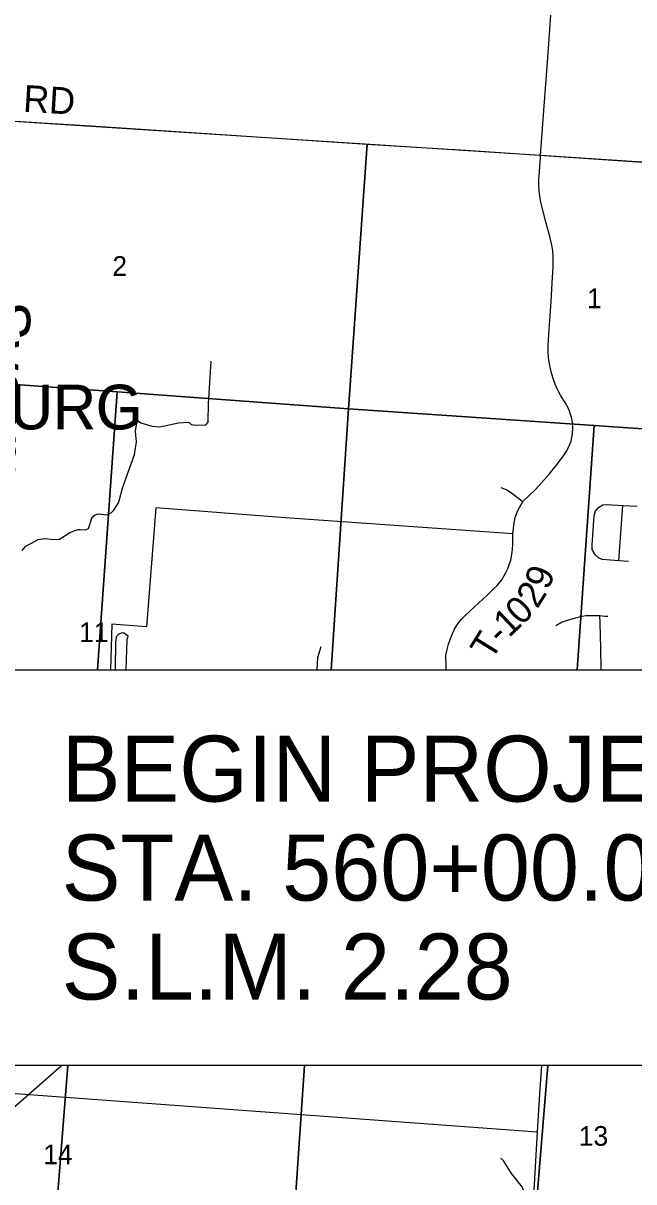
# Model space of a CAD drawing. Extents: x 0 to 34, y 0 to 26.1.
# Drawn here: x 28.22 to 29.516, y 18.306 to 20.765 of the extents above; entities that cross this region are included whole.
import ezdxf

# ---------------------------------------------------------------- set-up
doc = ezdxf.new("R2010")
doc.units = 0
for name, color, linetype in [('GM_X_Corporation_Text', 7, 'Continuous'), ('GM_X_Minor_Lake', 7, 'Continuous'), ('GM_X_Minor_River', 7, 'Continuous'), ('GM_X_Minor_River_Text', 7, 'Continuous'), ('GM_X_Section', 7, 'Continuous'), ('GM_X_Section_Text', 7, 'Continuous'), ('GM_X_Township_Road', 7, 'Continuous'), ('GM_X_Township_Road_Text', 7, 'Continuous'), ('SH_Data', 7, 'Continuous'), ('SH_Text', 7, 'Continuous')]:
    doc.layers.add(name, color=color, linetype=linetype)

msp = doc.modelspace()

# ---------------------------------------------------------------- linework, layer by layer
at = {"layer": 'GM_X_Minor_Lake'}
msp.add_line((28.4383, 19.3933), (28.4406, 19.4567), dxfattribs=at)
msp.add_lwpolyline([(28.4406, 19.4567), (28.4429, 19.4643), (28.4327, 19.4712), (28.4278, 19.4708), (28.4232, 19.4689), (28.4171, 19.4629), (28.416, 19.4511), (28.4159, 19.4306), (28.4152, 19.4173), (28.4154, 19.3933)], dxfattribs=at)
at = {"layer": 'GM_X_Minor_River'}
for points in [[(28.4071, 19.7271), (28.4124, 19.732), (28.4219, 19.7472), (28.4245, 19.7544), (28.431, 19.7786), (28.4565, 19.85), (28.4604, 19.8765), (28.4593, 19.8909), (28.4585, 19.9001), (28.4608, 19.9164), (28.4639, 19.9213), (28.4696, 19.9171), (28.4938, 19.9102), (28.5097, 19.909), (28.5498, 19.9173), (28.5714, 19.9184), (28.5763, 19.9138), (28.5866, 19.9119), (28.6078, 19.913), (28.6123, 19.9183), (28.6132, 19.9597), (28.6136, 19.9684), (28.619, 20.0481)], [(28.2176, 19.6459), (28.2259, 19.6554), (28.2453, 19.6663), (28.2517, 19.6694), (28.2661, 19.6716), (28.2846, 19.6693), (28.2971, 19.67), (28.3188, 19.6844), (28.3362, 19.6908), (28.3411, 19.6908), (28.3525, 19.6904), (28.3582, 19.6926), (28.3662, 19.7173), (28.373, 19.7222), (28.3794, 19.7241), (28.3984, 19.7222), (28.4071, 19.7271)], [(28.8438, 19.3933), (28.8453, 19.419), (28.8526, 19.4425)], [(29.2357, 17.9139), (29.2486, 17.9215), (29.2512, 17.9276), (29.2543, 17.9431), (29.2525, 18.0043), (29.2511, 18.0213), (29.248, 18.032), (29.2379, 18.0457), (29.2269, 18.0567), (29.2258, 18.0837), (29.2377, 18.1406), (29.248, 18.1747), (29.2575, 18.1948), (29.2704, 18.2142), (29.2852, 18.2282), (29.2886, 18.2331), (29.2886, 18.2396), (29.2883, 18.246), (29.2849, 18.2817), (29.2793, 18.2958), (29.2562, 18.3243), (29.24, 18.3502), (29.2336, 18.3566)]]:
    msp.add_lwpolyline(points, dxfattribs=at)
at = {"layer": 'GM_X_Section'}
for points in [[(27.9376, 20.5735), (28.3638, 20.5476), (28.9502, 20.5089), (28.9104, 19.9472), (28.4191, 19.9828), (27.9001, 20.0205)], [(28.9502, 20.5089), (29.1456, 20.4964), (29.1491, 20.4962), (29.6694, 20.4609), (29.9551, 20.4402), (29.9161, 19.8781), (29.4315, 19.9112), (28.9104, 19.9472)]]:
    msp.add_lwpolyline(points, close=True, dxfattribs=at)
for points in [[(28.1615, 19.0015), (27.8314, 19.025), (27.9001, 20.0205), (28.4191, 19.9828), (28.3774, 19.3933)], [(28.3774, 19.3933), (28.4191, 19.9828), (28.9104, 19.9472), (28.8738, 19.3933)], [(28.8738, 19.3933), (28.9104, 19.9472), (29.4315, 19.9112), (29.3959, 19.3933)], [(29.3959, 19.3933), (29.4315, 19.9112), (29.9161, 19.8781), (29.8466, 18.8822), (29.8402, 18.8827)], [(28.3147, 18.5533), (28.2704, 17.9878), (27.7604, 18.0248), (27.8314, 19.025), (28.1615, 19.0015)], [(28.8173, 18.5533), (28.776, 17.9511), (28.2704, 17.9878), (28.3147, 18.5533)], [(29.3334, 18.5533), (29.2811, 17.9144), (28.776, 17.9511), (28.8173, 18.5533)], [(29.825, 18.5533), (29.7809, 17.8804), (29.2811, 17.9144), (29.3334, 18.5533)]]:
    msp.add_lwpolyline(points, dxfattribs=at)
at = {"layer": 'GM_X_Township_Road'}
for p, q in [((29.4838, 19.6246), (29.4925, 19.742)), ((28.012, 18.5079), (29.3107, 18.4123)), ((29.3107, 18.4123), (29.297, 18.1618))]:
    msp.add_line(p, q, dxfattribs=at)
for points in [[(29.3177, 20.4844), (29.3247, 20.5799), (29.3328, 20.6825), (29.3477, 20.8931), (29.3482, 20.9)], [(29.9005, 20.446), (29.3177, 20.4844), (28.111, 20.5622)], [(29.1175, 19.3933), (29.1174, 19.4006), (29.1172, 19.4239), (29.1195, 19.4364), (29.1228, 19.4472), (29.1259, 19.4571), (29.1302, 19.4681), (29.1353, 19.4793), (29.1394, 19.4862), (29.1445, 19.4934), (29.1501, 19.5003), (29.1586, 19.5089), (29.2045, 19.5516), (29.2163, 19.5626), (29.2257, 19.5723), (29.2357, 19.5843), (29.2433, 19.5983), (29.2482, 19.6078), (29.2515, 19.6162), (29.2546, 19.6254), (29.2561, 19.6338), (29.2584, 19.6481), (29.2591, 19.6598), (29.2589, 19.6815), (29.2617, 19.7052), (29.264, 19.7166), (29.2695, 19.7312), (29.2807, 19.75), (29.3064, 19.7753), (29.3201, 19.7896), (29.3362, 19.8084), (29.3514, 19.8266), (29.3669, 19.8471), (29.3723, 19.8555), (29.3782, 19.8663), (29.3828, 19.8784), (29.3859, 19.8939), (29.3864, 19.9056), (29.3857, 19.9185), (29.3839, 19.929), (29.3783, 19.9462), (29.3703, 19.9602), (29.3611, 19.9743), (29.3538, 19.9879), (29.3489, 19.9993), (29.3445, 20.0113), (29.3403, 20.0251), (29.3367, 20.0422), (29.335, 20.0558), (29.334, 20.0672), (29.3341, 20.0807), (29.3357, 20.1055), (29.3402, 20.1744), (29.3424, 20.2143), (29.3448, 20.2478), (29.3451, 20.2563), (29.3448, 20.2682), (29.3437, 20.2827), (29.3419, 20.2943), (29.3378, 20.3124), (29.3301, 20.3411), (29.3236, 20.3657), (29.3193, 20.3825), (29.317, 20.393), (29.3149, 20.4095), (29.3142, 20.4234), (29.3144, 20.4343), (29.3148, 20.4415), (29.3176, 20.4806), (29.3177, 20.4844)], [(29.2336, 19.78), (29.2394, 19.7779), (29.2462, 19.7748), (29.2541, 19.77), (29.2807, 19.75)], [(29.2589, 19.6815), (28.7767, 19.7158), (28.5012, 19.7365), (28.4815, 19.4845), (28.4078, 19.4898), (28.405, 19.3933)], [(29.5043, 19.623), (29.4838, 19.6246), (29.4485, 19.6273), (29.4408, 19.6305), (29.4346, 19.6366), (29.4278, 19.6484), (29.4272, 19.6575), (29.4321, 19.7203), (29.4349, 19.7295), (29.4408, 19.7376), (29.4503, 19.7433), (29.4577, 19.744), (29.4925, 19.742), (29.5233, 19.7402)], [(29.3506, 19.487), (29.3626, 19.4941), (29.3749, 19.4985), (29.3823, 19.5004), (29.3954, 19.5042), (29.4055, 19.5072), (29.4145, 19.5086), (29.4246, 19.5086), (29.4342, 19.5083), (29.4435, 19.5086), (29.4544, 19.5072), (29.4607, 19.5069)], [(29.4467, 19.3933), (29.4456, 19.4383), (29.4446, 19.4927), (29.4435, 19.5086)], [(29.3202, 18.5533), (29.3157, 18.4929), (29.3107, 18.4123)]]:
    msp.add_lwpolyline(points, dxfattribs=at)
at = {"layer": 'SH_Data'}
for points in [[(28.1615, 19.3933), (29.8402, 19.3933), (29.8402, 18.5533), (28.1615, 18.5533)], [(28.1615, 18.6933), (27.1615, 17.5533), (28.3015, 18.5533), (28.1615, 18.5533)]]:
    msp.add_lwpolyline(points, close=True, dxfattribs=at)

# ---------------------------------------------------------------- texts
at = {"layer": 'GM_X_Corporation_Text'}
for p in [(27.4098, 19.9031), (27.411, 19.9034)]:
    msp.add_text('REYNOLDSBURG', height=0.094697, rotation=0, dxfattribs=at).set_placement(p)
at = {"layer": 'GM_X_Minor_River_Text'}
msp.add_text('Sycamore', height=0.09469, rotation=268.0002, dxfattribs=at).set_placement((28.1417, 20.1785))
at = {"layer": 'GM_X_Section_Text'}
for s, height, p in [('2', 0.0419, (28.4092, 20.229)), ('1', 0.0419, (29.4167, 20.1604)), ('11', 0.04186, (28.3388, 19.452)), ('13', 0.04186, (29.3992, 18.3829)), ('14', 0.04186, (28.2625, 18.3436))]:
    msp.add_text(s, height=height, rotation=0, dxfattribs=at).set_placement(p)
at = {"layer": 'GM_X_Township_Road_Text'}
for s, height, rotation, p in [('RD', 0.05682, 356.5467, (28.2189, 20.5776)), ('9', 0.0568, 68.2795, (29.3346, 19.5605)), ('2', 0.0568, 58.0091, (29.311, 19.5209)), ('0', 0.0568, 45.0771, (29.2776, 19.4852)), ('1', 0.0568, 43.3027, (29.2508, 19.4599)), ('T', 0.0568, 58.2858, (29.2139, 19.4107)), ('-', 0.0568, 43.2777, (29.2338, 19.4439))]:
    msp.add_text(s, height=height, rotation=rotation, dxfattribs=at).set_placement(p)
at = {"layer": 'SH_Text'}
for s, p in [('BEGIN PROJECT', (28.3015, 19.1133)), ('STA. 560+00.00', (28.3015, 18.9033)), ('S.L.M. 2.28', (28.3015, 18.6933))]:
    msp.add_text(s, height=0.14, dxfattribs=at).set_placement(p)

doc.saveas('drawing.dxf')
